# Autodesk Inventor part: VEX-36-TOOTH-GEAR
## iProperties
Created: 2007-08
Part Number: VEX-36-TOOTH-GEAR
Material: ABS Plastic
Document SubType Name: Modeling
Density: 1.06 g/cm^3
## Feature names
1. Base1
